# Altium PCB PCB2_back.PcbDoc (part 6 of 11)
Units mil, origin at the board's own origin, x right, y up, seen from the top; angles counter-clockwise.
Board outline 6299 x 3937 mil, 4 copper layers (TopLayer, GROUND, VCC, BottomLayer); 290 components, 470 nets, 2252 pads, 825 vias.
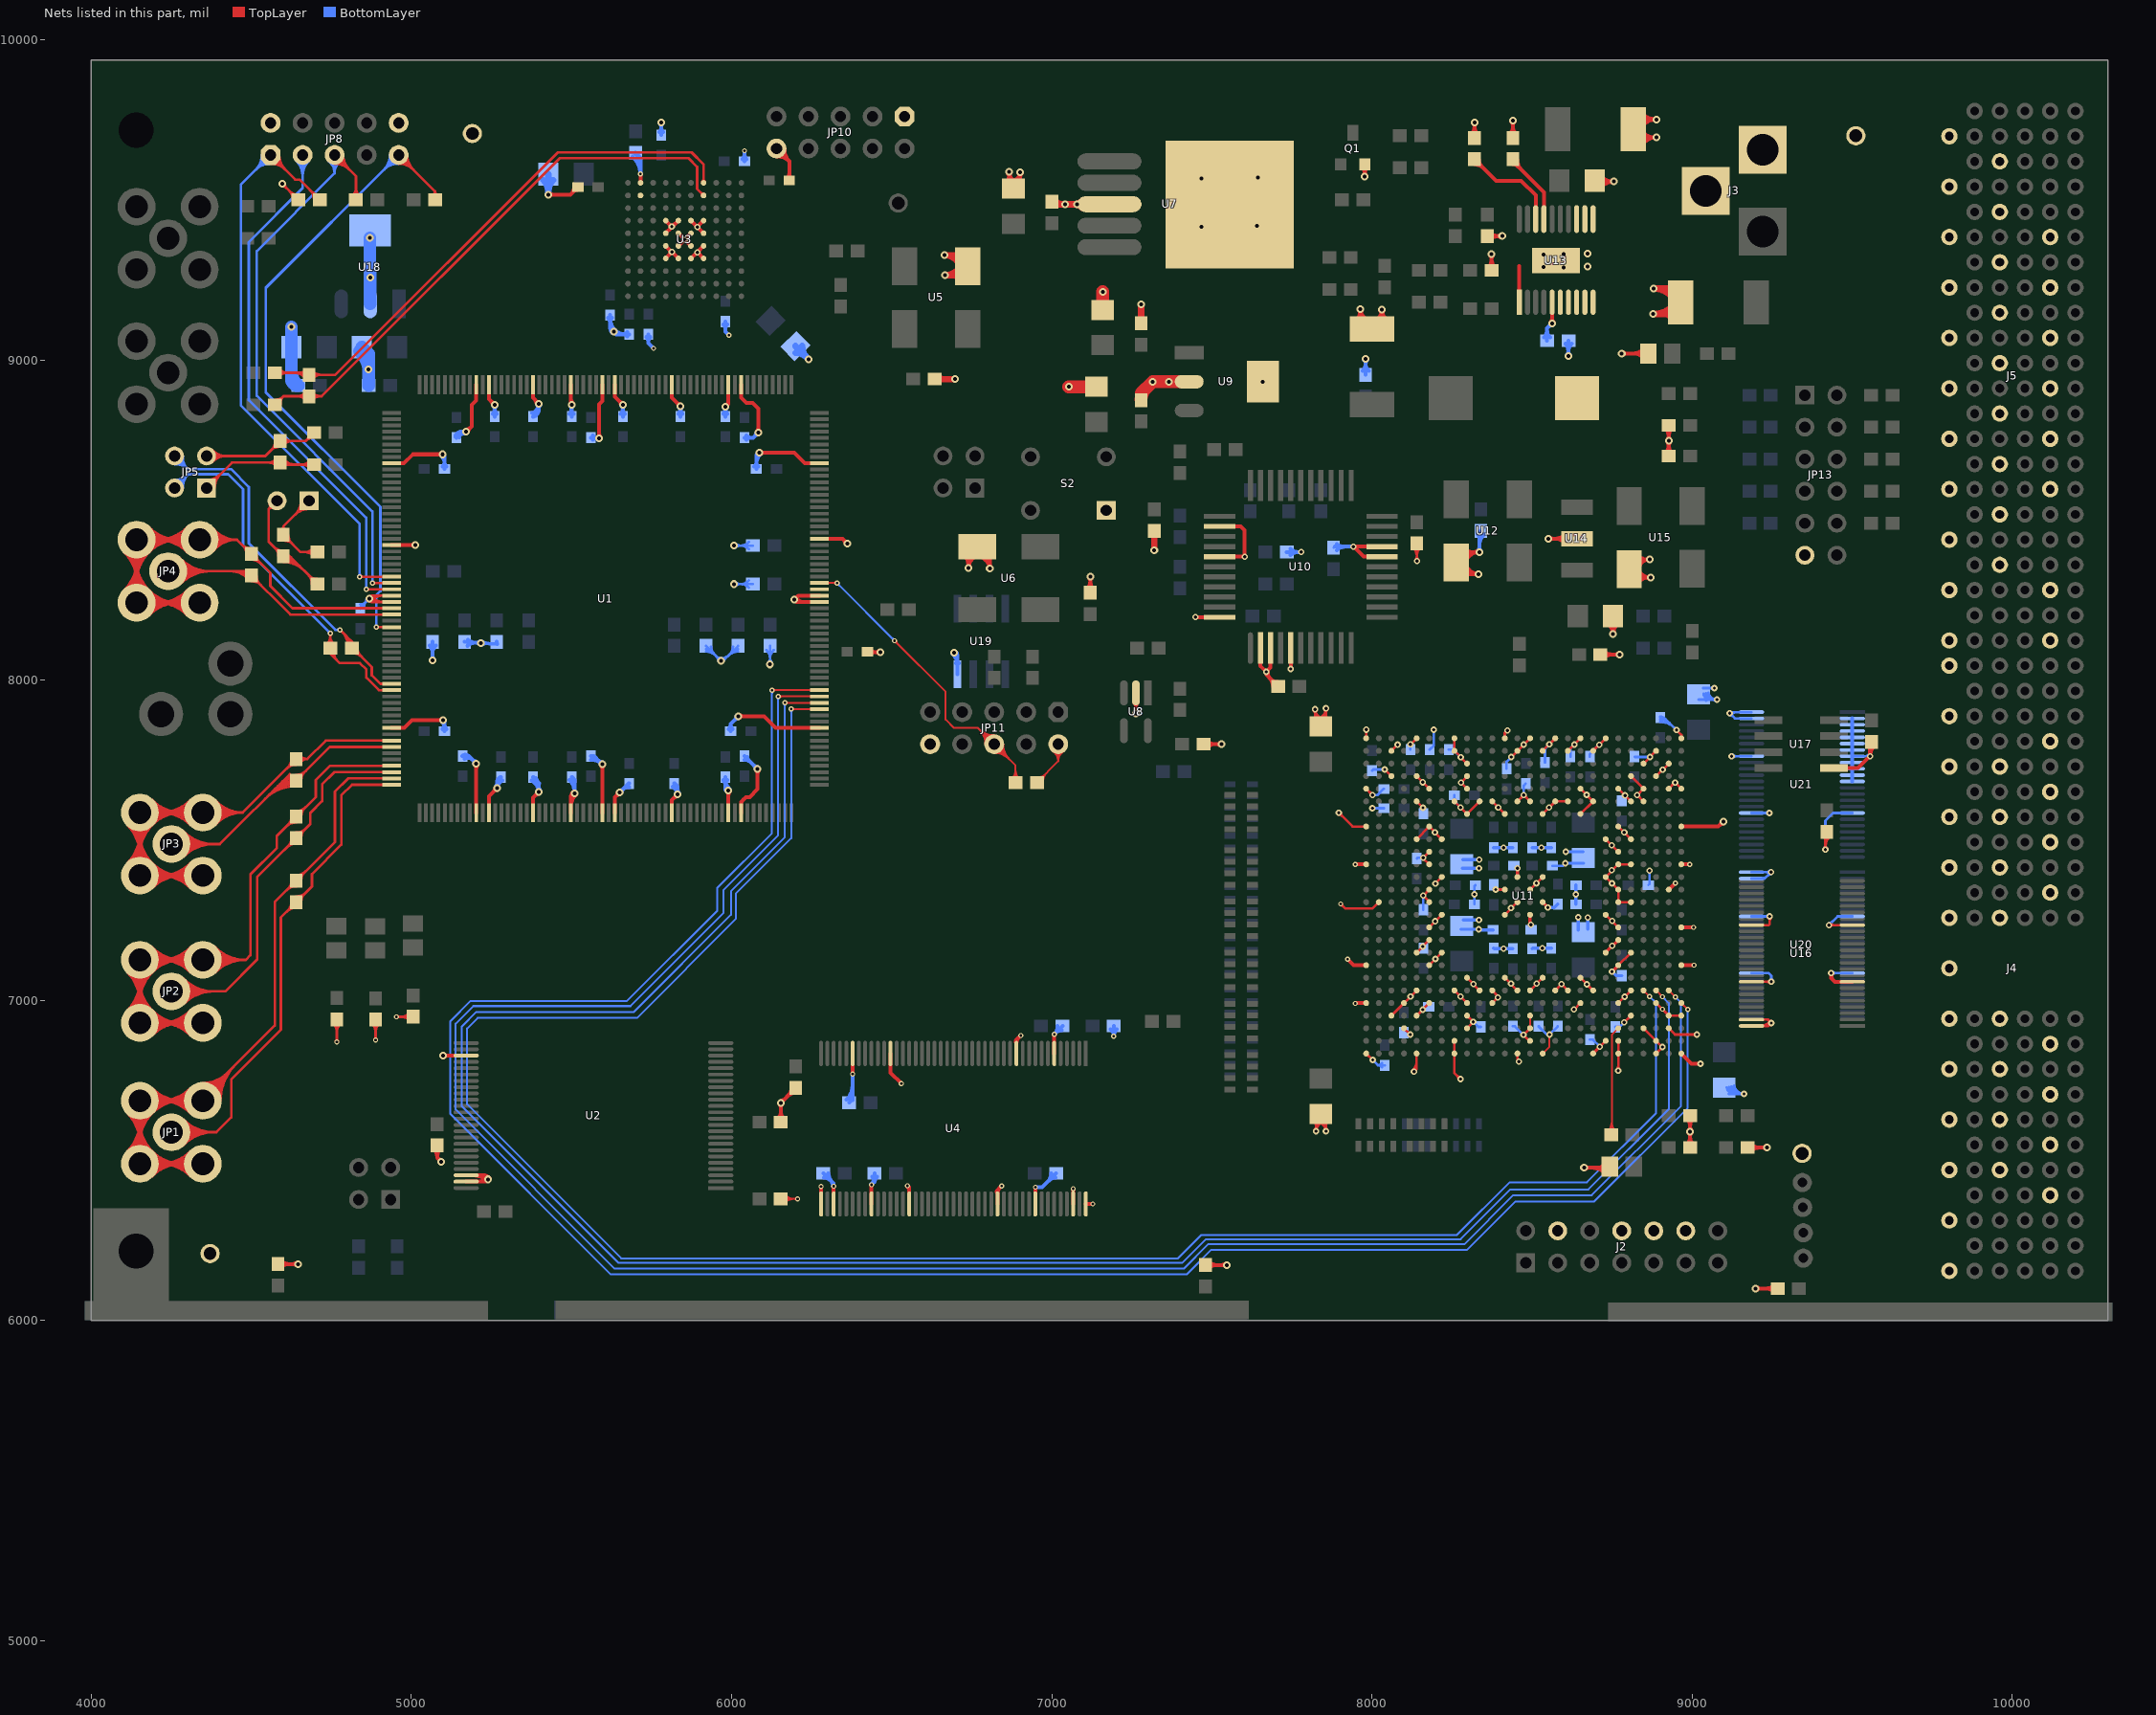
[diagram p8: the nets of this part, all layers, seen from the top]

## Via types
v1: diameter 16, hole 8, TopLayer to BottomLayer, 408 vias
v2: diameter 20, hole 10, TopLayer to BottomLayer, 221 vias
v3: diameter 24, hole 12, TopLayer to BottomLayer, 194 vias
v4: diameter 56.69, hole 56.69, TopLayer to BottomLayer, 2 vias

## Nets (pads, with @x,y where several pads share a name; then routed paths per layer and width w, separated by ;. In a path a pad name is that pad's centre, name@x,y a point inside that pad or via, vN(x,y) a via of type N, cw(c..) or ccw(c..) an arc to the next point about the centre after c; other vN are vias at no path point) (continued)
GND: (continued)
  BottomLayer w12: C42.1@5056.32,8107.89 cw(c5032.96,8084.53) 5066,8084.53 cw(c5099.04,8084.53) C42.1@5075.68,8107.89 ; v3@5061.76,8065.24 ccw(c5051.51,8075.49) 5066,8075.49 ccw(c5080.49,8075.49) v3@5070.24,8065.24 ; v3(5066,8061) C42.1@5066,8119.54 ; v3@5092.76,8700.76 cw(c5068.05,8676.05) 5102.99,8676.05 ; v3@5094.76,7870.76 cw(c5074.88,7850.88) C45.2@5102.99,7850.88 ; C45.2@5096.63,7846.36 ccw(c5081.26,7861.73) 5102.99,7861.73 ccw(c5124.72,7861.73) C45.2@5109.36,7846.36 ; C47.2@5096.63,8666.36 ccw(c5081.26,8681.73) 5102.99,8681.73 ccw(c5124.72,8681.73) C47.2@5109.36,8666.36 ; v3(5097,8705) 5102.99,8699.01 C47.2@5102.99,8660 ; v3(5099,7875) 5102.99,7871.01 C45.2@5102.99,7840 ; C48.2@5137.06,8760.09 cw(c5156.41,8756.28) 5156.41,8776 ; C48.2@5140,8757.01 5158.99,8776 ; C48.2@5140.26,8757.27 cw(c5171,8726.52) v3@5171,8770 ; C48.2@5140.23,8768.51 ccw(c5140.88,8794.11) 5158.99,8776 ; C48.2@5148.83,8757.77 cw(c5171,8753.41) v3(5171,8776) 5158.99,8776 ; C48.2@5149,8759.51 cw(c5164.69,8759.51) C48.2@5153.6,8770.6 ; C44.2@5158.11,7762.82 cw(c5168.58,7749.9) 5180.34,7761.66 ; C44.2@5160,7763.49 cw(c5160,7718.81) 5191.6,7750.4 ; C44.2@5165.67,7753.5 cw(c5177.01,7739.49) 5189.76,7752.24 ; C46.1@5166,8119.54 v3(5217,8116) 5267,8112 C50.2@5266,8119.54 ; C46.1@5174.98,8107.24 cw(c5201.08,8077.27) 5203.82,8116.91 ; C46.1@5176.32,8126.55 ccw(c5196.19,8143.84) 5194.37,8117.57 ; 5179.01,7762.99 v3(5202.46,7739.54) ; v3@5196.46,7739.54 ccw(c5181.97,7739.54) 5192.21,7749.79 ccw(c5202.46,7760.03) v3@5202.46,7745.54 ; v3@5212.47,8112.06 ccw(c5201.55,8102.55) 5202.55,8117 ccw(c5203.55,8131.45) v3@5213.06,8120.53 ; v3@5220.89,8111.43 cw(c5230.28,8100.41) 5231.44,8114.84 cw(c5232.59,8129.28) v3@5221.57,8119.89 ; C51.2@5253.64,8831.86 ccw(c5238.27,8847.22) 5260,8847.22 ccw(c5281.73,8847.22) C51.2@5266.36,8831.86 ; v3@5255.76,8854.76 cw(c5245.51,8844.51) 5260,8844.51 cw(c5274.49,8844.51) v3@5264.24,8854.76 ; C51.2@5260,8822.99 v3(5260,8859) ; v3@5262.76,7667.24 ccw(c5252.51,7677.49) 5267,7677.49 ccw(c5281.49,7677.49) v3@5271.24,7667.24 ; v3@5267,7660.42 cw(c5295.4,7660.42) C49.2@5283.71,7686.31 ; v3(5267,7663) 5267,7684.01 C49.2@5280,7697.01 ; 5267,7679.02 cw(c5287,7679.02) C49.2@5278.76,7697.24 ; C52.2@5375.45,7686.74 cw(c5352.45,7647.43) v3@5398,7647.43 ; C53.2@5377.06,8834 ccw(c5367.37,8862) v3(5397,8862) 5397,8839.99 ; C52.2@5380,7697.01 5398,7679.01 v3(5398,7651) ; C53.2@5380,8822.99 5397,8839.99 ; C52.2@5380.13,7685.51 cw(c5380.53,7659.04) 5399.25,7677.76 ; C53.2@5380.98,8822.66 ccw(c5373.2,8845.15) 5397,8845.15 ; C53.2@5381.03,8834.43 ccw(c5383.27,8853.72) 5397,8839.99 ; C52.2@5381.52,7697.1 cw(c5364.69,7668.35) 5398,7668.35 ; C52.2@5389,7694.51 ccw(c5404.69,7694.51) C52.2@5393.6,7683.41 ; C53.2@5389,8825.49 cw(c5404.69,8825.49) C53.2@5393.6,8836.59 ; v3@5392.76,8857.76 cw(c5382.51,8847.51) 5397,8847.51 cw(c5411.49,8847.51) v3@5401.24,8857.76 ; v3@5393.76,7655.24 ccw(c5383.51,7665.49) 5398,7665.49 ccw(c5412.49,7665.49) v3@5402.24,7655.24 ; C54.2@5493.64,7688.14 cw(c5456.54,7651.05) v3@5509,7651.05 ; C58.2@5493.64,8831.86 ccw(c5478.27,8847.22) 5500,8847.22 ccw(c5521.73,8847.22) C58.2@5506.36,8831.86 ; v3@5495.76,8855.76 cw(c5485.51,8845.51) 5500,8845.51 cw(c5514.49,8845.51) v3@5504.24,8855.76 ; C54.2@5500,7697.01 5509,7688.01 v3(5509,7646) ; C58.2@5500,8822.99 v3(5500,8860) ; C54.2@5502.12,7696.63 cw(c5485.52,7680.02) C54.2@5509,7680.02 ; v3@5504.76,7650.24 ccw(c5494.51,7660.49) 5509,7660.49 ccw(c5523.49,7660.49) v3@5513.24,7650.24 ; C56.2@5560,7751.49 cw(c5560,7699.57) v3@5596.72,7736.28 ; C56.2@5560,7762.99 5570.01,7762.99 v3(5596.16,7736.84) ; C56.2@5560,7763.49 cw(c5560,7740.54) 5576.23,7756.77 ; C57.2@5560,8757.01 5583.99,8757.01 v3(5586,8755) ; C57.2@5566.36,8750.64 cw(c5581.73,8735.28) 5581.73,8757.01 cw(c5581.73,8778.74) C57.2@5566.36,8763.37 ; C57.2@5566.67,8757.01 cw(c5566.67,8735.67) v3@5581.76,8750.76 ; v3@5590.16,7736.84 ccw(c5575.67,7736.84) 5585.91,7747.09 ccw(c5596.16,7757.33) v3@5596.16,7742.84 ; C59.1@5613.64,9131.14 cw(c5598.27,9115.77) 5620,9115.77 cw(c5641.73,9115.77) C59.1@5626.36,9131.14 ; 5620,9102.49 ccw(c5646.49,9102.49) v3@5627.76,9083.76 ; C59.1@5620,9131.46 ccw(c5675.46,9131.46) 5636.24,9092.24 ccw(c5665.8,9121.8) C62.1@5665.8,9080 ; C59.1@5620,9140 5620,9100 5640,9080 C62.1@5680,9080 ; v3@5626,9088 ccw(c5611.51,9088) 5621.76,9098.24 ccw(c5632,9108.49) v3@5632,9094 ; v3(5650,7649) 5678.01,7677.01 C60.2@5680,7677.01 ; v3@5650,7655 ccw(c5650,7669.49) 5660.24,7659.24 ccw(c5670.49,7649) v3@5656,7649 ; C61.2@5653.64,8831.86 ccw(c5638.27,8847.22) 5660,8847.22 ccw(c5681.73,8847.22) C61.2@5666.36,8831.86 ; v3@5655.76,8855.76 cw(c5645.51,8845.51) 5660,8845.51 cw(c5674.49,8845.51) v3@5664.24,8855.76 ; v3@5656.97,7655.97 cw(c5680,7632.94) C60.2@5680,7665.51 ; C61.2@5660,8822.99 v3(5660,8860) ; C62.1@5673.64,9073.64 ccw(c5658.27,9058.27) 5658.27,9080 ccw(c5658.27,9101.73) C62.1@5673.64,9086.36 ; C65.1@5733.64,9071.14 cw(c5718.27,9055.77) 5740,9055.77 cw(c5761.73,9055.77) C65.1@5746.36,9071.14 ; C65.1@5740,9080 5740,9052 v1(5756,9036) ; C66.1@5773.64,9710.86 ccw(c5758.27,9726.23) 5780,9726.23 ccw(c5801.73,9726.23) C66.1@5786.36,9710.86 ; v3@5775.76,9737.76 cw(c5765.51,9727.51) 5780,9727.51 cw(c5794.49,9727.51) v3@5784.24,9737.76 ; C66.1@5780,9702 v3(5780,9742) ; C63.2@5815.76,7666.57 cw(c5802.16,7641.14) v3@5831,7641.14 ; C63.2@5820,7677.01 5831,7666.01 v3(5831,7643) ; C63.2@5821.41,7677.15 cw(c5812.86,7661.16) C63.2@5831,7661.16 ; v3@5826.76,7647.24 ccw(c5816.51,7657.49) 5831,7657.49 ccw(c5845.49,7657.49) v3@5835.24,7647.24 ; C64.2@5833.64,8831.86 ccw(c5818.27,8847.22) 5840,8847.22 ccw(c5861.73,8847.22) C64.2@5846.36,8831.86 ; v3@5835.76,8850.76 cw(c5825.51,8840.51) 5840,8840.51 cw(c5854.49,8840.51) v3@5844.24,8850.76 ; C64.2@5840,8822.99 v3(5840,8855) ; C67.2@5973.64,7688.14 cw(c5958.27,7672.78) 5980,7672.78 cw(c6001.73,7672.78) C67.2@5986.36,7688.14 ; C69.2@5973.64,8831.86 ccw(c5958.27,8847.22) 5980,8847.22 ccw(c6001.73,8847.22) C69.2@5986.36,8831.86 ; C70.1@5973.64,9111.14 cw(c5958.27,9095.77) 5980,9095.77 cw(c6001.73,9095.77) C70.1@5986.36,9111.14 ; v3@5975.76,8849.76 cw(c5965.51,8839.51) 5980,8839.51 cw(c5994.49,8839.51) v3@5984.24,8849.76 ; 5980,7664.46 ccw(c5999.17,7664.46) v3@5985.62,7650.9 ; C67.2@5980,7693.43 ccw(c6028.14,7693.43) v3@5994.1,7659.38 ; C67.2@5980,7697.01 5980,7665 ; C69.2@5980,8822.99 v3(5980,8854) ; C70.1@5980,9120 5980,9089 v1(5992,9077) ; v3@5983.86,7655.31 ccw(c5970.67,7655.67) 5980,7665 ; v3@5989.69,7661.14 cw(c5989.33,7674.33) 5980,7665 ; v3(5989.86,7655.14) 5980,7665 ; C71.2@5990.64,7846.36 ccw(c5975.28,7861.73) 5997.01,7861.73 ccw(c6018.74,7861.73) C71.2@6003.37,7846.36 ; C71.2@5997.01,7840 5997.01,7863.01 v3(6021,7887) ; v3@6015,7887 cw(c6000.51,7887) 6010.76,7876.76 cw(c6021,7866.51) v3@6021,7881 ; C74.1@6033.64,9626.36 ccw(c6018.27,9641.73) 6040,9641.73 ccw(c6061.73,9641.73) C74.1@6046.36,9626.36 ; C75.2@6040,7751.49 cw(c6040,7723.73) 6059.63,7743.36 ; C75.2@6040,7762.99 v3(6081,7721.99) ; C77.2@6040,8757.01 6067.01,8757.01 v3(6083,8773) ; C74.1@6040,9620 v1(6040,9653) ; C77.2@6046.36,8750.64 cw(c6061.73,8735.28) 6061.73,8757.01 cw(c6061.73,8778.74) C77.2@6046.36,8763.37 ; C75.2@6049,7760.49 ccw(c6064.69,7760.49) C75.2@6053.6,7749.4 ; C73.2@6070.64,8666.36 ccw(c6055.28,8681.73) 6077.01,8681.73 ccw(c6098.74,8681.73) C73.2@6083.37,8666.36 ; v3@6075,7721.99 ccw(c6060.51,7721.99) 6070.76,7732.23 ccw(c6081,7742.48) v3@6081,7727.99 ; C73.2@6077.01,8660 6077.01,8701.01 ; C73.2@6077.01,8673.81 cw(c6122.19,8673.81) v3@6090.24,8705.76 ; v3@6077,8773 cw(c6062.51,8773) 6072.76,8762.76 cw(c6083,8752.51) v3@6083,8767 ; v3@6080.03,8709.42 cw(c6069.6,8708.42) 6077.01,8701.01 ; v3@6085.42,8704.03 ccw(c6084.42,8693.6) 6077.01,8701.01 ; v3(6086,8710) 6077.01,8701.01 ; C79.1@6286.54,6460 6318.6,6427.94 v1(6318.6,6419.4) ; C79.1@6288.5,6446.32 cw(c6288.5,6418.03) 6308.51,6438.03 ; C79.1@6302.19,6460 ccw(c6339.98,6460) 6313.26,6433.28 ; 6309.15,6437.39 cw(c6291.17,6419.4) v1@6316.6,6419.4 ; C80.1@6358.83,6689.68 ccw(c6313.37,6735.13) 6377.65,6735.13 ; C80.1@6367.31,6681.19 ccw(c6342.34,6706.16) 6377.65,6706.16 ; C80.1@6377.65,6688.88 v1(6377.65,6769.35) ; v1@6435.3,6425.12 ccw(c6408.16,6452.26) C81.1@6446.54,6452.26 ; v1(6436.71,6423.71) 6446.54,6433.54 ; C81.1@6438.63,6448.83 cw(c6427.79,6433.54) 6446.54,6433.54 ; C81.1@6446.54,6460 6446.54,6433.54 ; C81.1@6454.45,6448.83 ccw(c6465.28,6433.54) 6446.54,6433.54 ; v3@6690.76,8080.76 cw(c6656.37,8046.37) U19.4@6705,8046.37 ; v3(6695,8085) 6705,8075 ; v3@6695.1,8079 cw(c6695.34,8065.34) 6705,8075 ; v3@6699.24,8089.24 cw(c6685.34,8075.34) 6705,8075.34 ; U19.4@6700.89,8053.24 ccw(c6690.97,8063.16) 6705,8063.16 ccw(c6719.03,8063.16) U19.4@6709.11,8053.24 ; v3@6701,8084.9 ccw(c6714.66,8084.66) 6705,8075 ; U19.4@6705,8017.64 6705,8075 ; v1(6948.52,6416.52) 6969.98,6416.52 C82.1@7013.46,6460 ; 6986.74,6433.28 ccw(c6960.02,6460) C82.1@6997.81,6460 ; 6991.49,6438.03 cw(c7011.5,6418.03) C82.1@7011.5,6446.32 ; v1(7007.57,6894.11) C83.1@7033.46,6920 ; v1@7008.56,6895.1 ccw(c6986.07,6917.58) C83.1@7017.83,6919.27 ; v1@7011.49,6898.03 cw(c7031.5,6878.03) C83.1@7031.5,6906.32 ; C84.1@7183.89,6910.22 cw(c7161.64,6887.47) v1(7193.46,6887.46) ; C84.1@7193.46,6920 v1(7193.46,6887.46) ; C84.1@7203.03,6910.22 ccw(c7225.29,6887.47) v1(7193.46,6887.46) ; C86.1@7733.46,8400 v2(7779,8400) ; C86.1@7745.11,8390.32 cw(c7768.47,8366.96) 7768.47,8400 cw(c7768.47,8433.04) C86.1@7745.11,8409.68 ; C89.1@7883.46,8416.93 v2(7941.93,8416.93) ; C89.1@7889.68,8405.76 cw(c7916.65,8378.78) 7916.65,8416.93 ; C89.1@7889.68,8425.11 ccw(c7909.43,8444.86) 7909.43,8416.93 ; C92.1@7970.32,8965.11 ccw(c7946.96,8988.47) 7980,8988.47 ccw(c8013.04,8988.47) C92.1@7989.68,8965.11 ; v3@7975.76,8998.76 cw(c7965.51,8988.51) 7980,8988.51 cw(c7994.49,8988.51) v3@7984.24,8998.76 ; C92.1@7980,8953.46 v3(7980,9003) ; C117.1@8330.32,8454.89 cw(c8319.03,8443.6) 8335,8443.6 ; v3@8330.76,8404.24 ccw(c8320.51,8414.49) 8335,8414.49 ccw(c8349.49,8414.49) v3@8339.24,8404.24 ; v3(8335,8400) 8335,8461.54 C117.1@8340,8466.54 ; 8335,8419.46 cw(c8385.11,8419.46) C117.1@8349.68,8454.89 ; U21.12@9500,7683.47 U21.2@9500,7880.31
  BottomLayer w20: v3@4866.54,8969.46 v3@4866.54,8970 ; C55.2@5412,9560.86 cw(c5375.3,9524.17) 5427.2,9524.17 cw(c5479.09,9524.17) C55.2@5442.4,9560.86 ; v3(5427.2,9516.2) C55.2@5427.2,9580 ; C78.2@6198.97,9021.84 cw(c6198.97,8969.95) 6235.67,9006.64 cw(c6272.37,9043.34) C78.2@6220.47,9043.34 ; C78.2@6198.97,9043.34 v3(6240.31,9002)
  BottomLayer w40: 4624.88,8966.76 ccw(c4691.33,8966.76) C39.1@4644.34,8919.78 ; v3(4624.88,9102.88) 4624.88,8941.65 ; C39.1@4644.53,8919.69 cw(c4646.98,8941.65) 4624.88,8941.65 ; C39.1@4646.54,8920 4624.88,8941.65 ; C43.2@4837.55,9027.21 cw(c4787.45,8966.71) v3@4866,8966.71 ; C43.2@4844.88,9040 4866,9018.88 v3(4866,8970) 4866.54,8969.46 C41.1@4866.54,8920 ; v3(4870,9381) U18.2@4871,9175
  other v1: 8906.68,6972.06
  other v2: 8158.11,6970.99 8789,7011 8120.43,7012.05 8276.51,7011.68 8316.5,7050.42 8671,7050 8434,7052 8514,7052 8198.14,7129.13 8411,7160.99 8532,7162.99 8158.45,7168.18 8750,7170 8197,7247 8750,7248 8434,7288 8320,7331 8637.01,7331 8749.46,7365.5 8513.29,7365.54 8749,7406 8411,7477.01 8529,7477.01 8748.71,7484.36 8788,7524 8196.61,7524.65 8394,7602 8553.21,7602.31 8790,7640 8670.04,7641.77 8158.49,7680.88 8907.77,7720.65 5813.2,9337.06
  other v3: 8993.47,6590 8926.54,8747 7366,8932 7659,8932 5632,9088 4871,9257 8599,9288 8536,9290 8673,9292 8535,9329 8599,9330 8673,9332 7467,9415 7641,9419 7042,9486 7078,9486 7467,9567 7643,9569
GP02: R51.1 U11.C6 | length 445.9
  TopLayer w6: R51.1@8736.71,6591.8 ccw(c8707.03,6621.48) 8749,6621.48 ; R51.1@8740.95,6587.56 ccw(c8721.51,6606.99) 8749,6606.99 ; R51.1@8746.54,6580 8749,6582.46 8749,6892.59 U11.C6@8769.15,6912.74 ; 8749,6604.6 ccw(c8773.1,6604.6) R51.1@8756.06,6587.56 ; 8749,6619.08 ccw(c8787.59,6619.08) R51.1@8760.3,6591.8
GP04: U1.13 U11.F4 | length 6581.4
  TopLayer w6: v1(6186,7909.51) U1.13@6274.31,7909.51 ; v1@6189.54,7905.98 cw(c6198.07,7897.44) 6198.07,7909.51 cw(c6198.07,7921.58) v1@6189.54,7913.05 ; U1.13@6248.63,7907.46 ccw(c6243.67,7902.5) 6243.67,7909.51 ccw(c6243.67,7916.53) U1.13@6248.63,7911.57 ; U11.F4@8847.89,7030.85 v1(8867,7011.74)
  BottomLayer w6: v1@6182.46,7905.98 cw(c6173.93,7897.44) 6186,7897.44 cw(c6198.07,7897.44) v1@6189.54,7905.98 ; v1(6186,7909.51) 6186,7506 6013,7333 6013,7254 5704,6945 5207,6945 5174,6912 5174,6675 5655,6194 7394,6194 7467,6267 8265,6267 8430,6432 8671,6432 8887,6648 8887,6991.74 v1(8867,7011.74)
GP05: U1.14 U11.F3 | length 6681.7
  TopLayer w6: v1(6166,7929.2) U1.14@6274.31,7929.2 ; v1@6169.54,7925.66 cw(c6178.07,7917.13) 6178.07,7929.2 cw(c6178.07,7941.27) v1@6169.54,7932.73 ; U1.14@6248.63,7927.14 ccw(c6243.67,7922.18) 6243.67,7929.2 ccw(c6243.67,7936.21) U1.14@6248.63,7931.25 ; U11.F3@8887.26,7030.85 v1(8907,7011.11)
  BottomLayer w6: v1@6162.46,7925.66 cw(c6153.93,7917.13) 6166,7917.13 cw(c6178.07,7917.13) v1@6169.54,7925.66 ; v1(6166,7929.2) 6166,7509 5998,7341 5998,7267 5695,6964 5203,6964 5157,6918 5157,6670 5647,6180 7407,6180 7481,6254 8277,6254 8432,6409 8676,6409 8927,6660 8927,6991.11 v1(8907,7011.11)
GP06: U1.15 U11.F2 | length 6792.9
  TopLayer w6: v1(6145,7948.88) U1.15@6274.31,7948.88 ; v1@6148.54,7945.35 cw(c6157.07,7936.81) 6157.07,7948.88 cw(c6157.07,7960.95) v1@6148.54,7952.42 ; U1.15@6248.63,7946.83 ccw(c6243.67,7941.87) 6243.67,7948.88 ccw(c6243.67,7955.9) U1.15@6248.63,7950.94 ; U11.F2@8926.63,7030.85 v1(8947,7010.48)
  BottomLayer w6: v1@6141.46,7945.35 cw(c6132.93,7936.81) 6145,7936.81 cw(c6157.07,7936.81) v1@6148.54,7945.35 ; v1(6145,7948.88) 6145,7515 5974,7344 5974,7272 5684,6982 5193,6982 5138,6927 5138,6659 5635,6162 7412,6162 7488,6238 8288,6238 8441.27,6391.27 8686.27,6391.27 8965,6670 8965,6992.48 v1(8947,7010.48)
GP07: U1.16 U11.E1 | length 6846.1
  TopLayer w6: v1(6126,7968.57) U1.16@6274.31,7968.57 ; v1@6129.54,7965.03 cw(c6138.07,7956.5) 6138.07,7968.57 cw(c6138.07,7980.64) v1@6129.54,7972.1 ; U1.16@6248.63,7966.51 ccw(c6243.67,7961.55) 6243.67,7968.57 ccw(c6243.67,7975.58) U1.16@6248.63,7970.62 ; U11.E1@8966,6991.48 v1(8986,6971.48)
  BottomLayer w6: v1@6122.46,7965.03 cw(c6113.93,7956.5) 6126,7956.5 cw(c6138.07,7956.5) v1@6129.54,7965.03 ; v1(6126,7968.57) 6126,7522 5955,7351 5955,7280 5673,6998 5185,6998 5121,6934 5121,6646 5623,6144 7421,6144 7497,6220 8296,6220 8448.02,6372.02 8694.02,6372.02 8986,6664 v1(8986,6971.48)
IN1+: C2.1 R13.1 U3.A7 | length 1926
  TopLayer w8: C2.1@4573.46,8960 4673.46,8960 R13.1@4680,8953.46 4762.13,8953.46 5456.67,9648 5875,9648 5912.22,9610.78 U3.A7@5912.22,9553 ; C2.1@4586.52,8948.91 cw(c4613.3,8922.13) 4613.3,8960 cw(c4613.3,8997.87) C2.1@4586.52,8971.09 ; 4631.11,8960 cw(c4631.11,8906.54) R13.1@4668.91,8944.34 ; 4650.42,8960 cw(c4650.42,8925.85) R13.1@4674.57,8950 ; 4653.16,8960 ccw(c4653.16,8982.27) R13.1@4668.91,8966.52 ; R13.1@4691.09,8942.37 cw(c4717.87,8915.6) 4717.87,8953.46 cw(c4717.87,8991.33) R13.1@4691.09,8964.56 ; U3.A7@5908.79,9556.44 ccw(c5900.49,9564.73) 5912.22,9564.73 ccw(c5923.95,9564.73) U3.A7@5915.66,9556.44
IN1-: C1.1 R13.2 U3.B7 | length 1937.2
  TopLayer w8: C1.1@4573.46,8860 4600,8886.54 ; C1.1@4575.43,8875.68 ccw(c4575.43,8908.8) 4598.85,8885.38 ; C1.1@4591.04,8861.53 cw(c4621.98,8864.56) 4600,8886.53 ; R13.2@4668.91,8875.44 ccw(c4642.13,8848.67) 4642.13,8886.54 ccw(c4642.13,8924.4) R13.2@4668.91,8897.63 ; R13.2@4691.09,8875.44 cw(c4717.87,8848.67) 4717.87,8886.54 cw(c4717.87,8924.4) R13.2@4691.09,8897.63 ; U3.B7@5907.36,9513.63 ccw(c5895.63,9513.63) 5903.93,9521.92 ccw(c5912.22,9530.22) U3.B7@5912.22,9518.49 ; U3.B7@5912.22,9513.63 5892,9533.85 5892,9603 5865,9630 5463,9630 4719.54,8886.54 4600,8886.54
IN2+: R66.1 U3.A2 | length 205
  TopLayer w12: U3.A2@5715.37,9553 v1(5715.37,9580.37)
  BottomLayer w12: R66.1@5690.76,9634.47 cw(c5639.55,9578.56) v1@5715.37,9578.56 ; R66.1@5698.86,9643.32 cw(c5664.52,9605.82) 5715.37,9605.82 ; R66.1@5700,9646.54 5715.37,9631.17 v1(5715.37,9580.37)
IN2-: U3.B2
JTAG_TCK: JP8.1 R14.2 U1.147 | length 2277.4
  TopLayer w8: JP8.1@4560,9613 cw(c4560,9547.82) 4606.09,9593.91 cw(c4652.18,9640) JP8.1@4587,9640 ; JP8.1@4560,9621 cw(c4560,9575.13) 4592.44,9607.56 cw(c4624.87,9640) JP8.1@4579,9640 ; JP8.1@4560,9640 4637,9563 4650.46,9563 R14.2@4713.46,9500 ; 4683.33,9530.14 cw(c4653.19,9500) R14.2@4695.81,9500 ; 4688.08,9525.38 ccw(c4711.5,9548.8) R14.2@4711.5,9515.68 ; R14.2@4696.99,9516.48 cw(c4680.51,9500) R14.2@4703.81,9500 ; v1(4838.1,8322.9) U1.147@4937.69,8322.9 ; v1@4840.93,8320.07 cw(c4847.76,8313.24) 4847.76,8322.9 cw(c4847.76,8332.55) v1@4840.93,8325.73
  BottomLayer w8: JP8.1@4533,9640 cw(c4467.82,9640) 4513.91,9593.91 cw(c4560,9547.82) JP8.1@4560,9613 ; JP8.1@4541,9640 cw(c4495.13,9640) 4527.56,9607.56 cw(c4560,9575.13) JP8.1@4560,9621 ; JP8.1@4560,9640 4467,9547 4467,8858 4838.1,8486.9 v1(4838.1,8322.9) ; v1@4835.27,8325.73 ccw(c4828.45,8332.55) 4838.1,8332.55 ccw(c4847.76,8332.55) v1@4840.93,8325.73
JTAG_TDI: JP8.9 R18.1 U1.155 | length 2445.3
  TopLayer w8: v1(4890,8165.42) U1.155@4937.69,8165.42 ; v1@4892.83,8162.59 cw(c4899.66,8155.76) 4899.66,8165.42 cw(c4899.66,8175.07) v1@4892.83,8168.25 ; JP8.9@4960,9613 cw(c4960,9547.82) 5006.09,9593.91 cw(c5052.18,9640) JP8.9@4987,9640 ; JP8.9@4960,9621 cw(c4960,9575.13) 4992.44,9607.56 cw(c5024.87,9640) JP8.9@4979,9640 ; JP8.9@4960,9640 5073.46,9526.54 ; R18.1@5065.9,9513.74 ccw(c5058.86,9526.53) 5073.46,9526.53 ; R18.1@5073.46,9500 5073.46,9526.54 ; R18.1@5081.03,9513.74 cw(c5088.07,9526.53) 5073.46,9526.53
  BottomLayer w8: v1@4887.17,8168.25 ccw(c4880.34,8175.07) 4890,8175.07 ccw(c4899.66,8175.07) v1@4892.83,8168.25 ; v1(4890,8165.42) 4890,8265 4903,8278 4903,8541 4545,8899 4545,9225 JP8.9@4960,9640 ; JP8.9@4933,9640 cw(c4867.82,9640) 4913.91,9593.91 cw(c4960,9547.82) JP8.9@4960,9613 ; JP8.9@4941,9640 cw(c4895.13,9640) 4927.56,9607.56 cw(c4960,9575.13) JP8.9@4960,9621
JTAG_TDO: JP8.3 U1.149 | length 1861.9
  TopLayer w8: v1(4858.47,8283.53) U1.149@4937.69,8283.53 ; v1@4861.3,8280.7 cw(c4868.13,8273.87) 4868.13,8283.53 cw(c4868.13,8293.18) v1@4861.3,8286.36
  BottomLayer w8: JP8.3@4640.91,9620.91 cw(c4594.82,9574.82) 4660,9574.82 cw(c4725.18,9574.82) JP8.3@4679.09,9620.91 ; JP8.3@4646.56,9626.56 cw(c4614.13,9594.13) 4660,9594.13 cw(c4705.87,9594.13) JP8.3@4673.44,9626.56 ; JP8.3@4660,9640 4660,9536 4492,9368 4492,8874 4858.47,8507.53 v1(4858.47,8283.53) ; v1@4855.64,8286.36 ccw(c4848.82,8293.18) 4858.47,8293.18 ccw(c4868.13,8293.18) v1@4861.3,8286.36
JTAG_TMS: JP8.5 R15.1 U1.148 | length 2219.2
  TopLayer w8: JP8.5@4760,9613 cw(c4760,9547.82) 4806.09,9593.91 cw(c4852.18,9640) JP8.5@4787,9640 ; JP8.5@4760,9621 cw(c4760,9575.13) 4792.44,9607.56 cw(c4824.87,9640) JP8.5@4779,9640 ; JP8.5@4760,9640 4826.54,9573.46 R15.1@4826.54,9500 ; R15.1@4815.44,9511.09 ccw(c4788.67,9537.87) 4826.54,9537.87 ccw(c4864.4,9537.87) R15.1@4837.63,9511.09 ; v1(4878,8303.21) U1.148@4937.69,8303.21 ; v1@4880.83,8300.38 cw(c4887.66,8293.56) 4887.66,8303.21 cw(c4887.66,8312.87) v1@4880.83,8306.04
  BottomLayer w8: JP8.5@4742.9,9619.11 cw(c4713.34,9583) 4760,9583 ; JP8.5@4747.96,9625.3 cw(c4727.16,9599.89) 4760,9599.89 cw(c4792.84,9599.89) JP8.5@4772.04,9625.3 ; JP8.5@4760,9640 4760,9583 ; JP8.5@4777.1,9619.11 ccw(c4806.66,9583) 4760,9583 ; v1@4875.17,8306.04 ccw(c4868.34,8312.87) 4878,8312.87 ccw(c4887.66,8312.87) v1@4880.83,8306.04 ; v1(4878,8303.21) 4878,8527 4517,8888 4517,9340 4760,9583
LVDS1_INN: JP1.2 R1.1 U1.179 | length 6666.2
  TopLayer w8: JP1.2@4112.65,6528.5 ccw(c4018.66,6622.49) 4151.57,6622.49 ccw(c4284.49,6622.49) 4190.5,6528.5 ccw(c4284.49,6622.49) 4284.49,6489.57 ccw(c4284.49,6356.66) JP1.2@4190.5,6450.65 ; JP1.2@4112.65,6647.5 cw(c4018.66,6553.51) 4151.57,6553.51 cw(c4284.49,6553.51) 4190.5,6647.5 cw(c4284.49,6553.51) 4284.49,6686.43 cw(c4284.49,6819.34) JP1.2@4190.5,6725.35 ; JP1.2@4118.3,6522.85 ccw(c4037.97,6603.18) 4151.57,6603.18 ccw(c4265.18,6603.18) 4184.85,6522.85 ccw(c4265.18,6603.18) 4265.18,6489.57 ccw(c4265.18,6375.97) JP1.2@4184.85,6456.3 ; JP1.2@4118.3,6653.15 cw(c4037.97,6572.82) 4151.57,6572.82 cw(c4265.18,6572.82) 4184.85,6653.15 cw(c4265.18,6572.82) 4265.18,6686.43 cw(c4265.18,6800.03) JP1.2@4184.85,6719.7 ; JP1.2@4123.96,6517.19 ccw(c4057.29,6583.86) 4151.57,6583.86 ccw(c4245.86,6583.86) 4179.19,6517.19 ccw(c4245.86,6583.86) 4245.86,6489.58 ccw(c4245.86,6395.29) JP1.2@4179.19,6461.96 ; JP1.2@4123.96,6658.81 cw(c4057.29,6592.14) 4151.57,6592.14 cw(c4245.86,6592.14) 4179.19,6658.81 cw(c4245.86,6592.14) 4245.86,6686.42 cw(c4245.86,6780.71) JP1.2@4179.19,6714.04 ; JP1.2@4129.62,6511.53 ccw(c4076.6,6564.55) 4151.57,6564.55 ccw(c4226.55,6564.55) 4173.53,6511.53 ccw(c4226.55,6564.55) 4226.55,6489.57 ccw(c4226.55,6414.6) JP1.2@4173.53,6467.62 ; JP1.2@4129.62,6664.47 cw(c4076.6,6611.45) 4151.57,6611.45 cw(c4226.55,6611.45) 4173.53,6664.47 cw(c4226.55,6611.45) 4226.55,6686.43 cw(c4226.55,6761.4) JP1.2@4173.53,6708.38 ; JP1.2@4309.5,6450.65 ccw(c4215.51,6356.66) 4215.51,6489.57 ccw(c4215.51,6622.49) JP1.2@4309.5,6528.5 ; JP1.2@4309.5,6647.5 ccw(c4215.51,6553.51) 4215.51,6686.43 ccw(c4215.51,6819.34) JP1.2@4309.5,6725.35 ; JP1.2@4315.15,6456.3 ccw(c4234.82,6375.97) 4234.82,6489.57 ccw(c4234.82,6603.18) JP1.2@4315.15,6522.85 ; JP1.2@4315.15,6653.15 ccw(c4234.82,6572.82) 4234.82,6686.43 ccw(c4234.82,6800.03) JP1.2@4315.15,6719.7 ; JP1.2@4320.81,6461.96 ccw(c4254.14,6395.29) 4254.14,6489.57 ccw(c4254.14,6583.86) JP1.2@4320.81,6517.19 ; JP1.2@4320.81,6658.81 ccw(c4254.14,6592.14) 4254.14,6686.42 ccw(c4254.14,6780.71) JP1.2@4320.81,6714.04 ; JP1.2@4326.47,6467.62 ccw(c4273.45,6414.6) 4273.45,6489.57 ccw(c4273.45,6564.55) JP1.2@4326.47,6511.53 ; JP1.2@4326.47,6664.47 ccw(c4273.45,6611.45) 4273.45,6686.43 ccw(c4273.45,6761.4) JP1.2@4326.47,6708.38 ; JP1.2@4348.43,6489.57 JP1.2@4151.57,6489.57 JP1.2@4151.57,6686.43 4338,6686.43 4573,6921.43 4573,7306.46 4761,7494.46 4761,7652 4801.98,7692.98 U1.179@4937.69,7692.98 ; JP1.2@4348.43,6725.48 ccw(c4348.43,6794.6) 4397.3,6745.72 ; JP1.2@4348.43,6733.48 ccw(c4348.43,6821.91) 4410.96,6759.38 ; JP1.2@4348.43,6741.48 ccw(c4348.43,6849.23) 4424.61,6773.04 ; JP1.2@4371.48,6686.43 cw(c4452.31,6686.43) 4395.15,6743.58 ; JP1.2@4379.48,6686.43 cw(c4479.62,6686.43) 4408.81,6757.24 ; JP1.2@4387.48,6686.43 cw(c4506.94,6686.43) 4422.47,6770.89 ; JP1.2@4395.48,6686.43 cw(c4534.25,6686.43) 4436.12,6784.55 ; JP1.2@4403.48,6686.43 cw(c4561.56,6686.43) 4449.78,6798.21 ; 4609.86,7343.33 cw(c4640,7313.19) R1.1@4640,7355.81 ; 4614.62,7348.08 ccw(c4591.2,7371.5) R1.1@4624.31,7371.5 ; R1.1@4623.52,7356.98 cw(c4640,7340.51) R1.1@4640,7363.81 ; R1.1@4640,7383.12 ccw(c4640,7406.42) R1.1@4656.48,7389.94 ; R1.1@4640,7391.12 ccw(c4640,7433.74) 4670.14,7403.6 ; R1.1@4655.69,7375.43 cw(c4688.8,7375.43) 4665.38,7398.85
LVDS1_INP: JP1.1 R1.2 U1.180 | length 2333.7
  TopLayer w8: JP1.1@4250,6588 4391,6588 4437,6634 4437,6753 4592,6908 4592,7258.54 4689,7355.54 4689,7394 4781,7486 4781,7640 4814.29,7673.29 U1.180@4937.69,7673.29 ; JP1.1@4271.96,6566.04 cw(c4324.97,6513.03) 4324.97,6588 cw(c4324.97,6662.97) JP1.1@4271.96,6609.96 ; JP1.1@4277.62,6560.38 cw(c4344.29,6493.71) 4344.29,6588 cw(c4344.29,6682.29) JP1.1@4277.62,6615.62 ; JP1.1@4283.27,6554.73 cw(c4363.6,6474.4) 4363.6,6588 cw(c4363.6,6701.6) JP1.1@4283.27,6621.27 ; JP1.1@4288.93,6549.07 cw(c4382.91,6455.09) 4382.91,6588 cw(c4382.91,6720.91) JP1.1@4288.93,6626.93 ; 4609.86,7276.4 cw(c4640,7246.26) R1.2@4640,7288.88 ; 4614.62,7281.15 ccw(c4591.2,7304.57) R1.2@4624.31,7304.57 ; R1.2@4623.52,7290.06 cw(c4640,7273.58) R1.2@4640,7296.88 ; R1.2@4640,7316.19 ccw(c4640,7339.49) R1.2@4656.48,7323.02 ; R1.2@4640,7324.19 ccw(c4640,7366.81) 4670.14,7336.67 ; R1.2@4655.69,7308.5 cw(c4688.8,7308.5) 4665.38,7331.92
LVDS2_INN: JP2.2 R7.1 U1.177 | length 6359
  TopLayer w8: JP2.2@4112.65,6968.5 ccw(c4018.66,7062.49) 4151.57,7062.49 ccw(c4284.49,7062.49) 4190.5,6968.5 ccw(c4284.49,7062.49) 4284.49,6929.57 ccw(c4284.49,6796.66) JP2.2@4190.5,6890.65 ; JP2.2@4112.65,7087.5 cw(c4018.66,6993.51) 4151.57,6993.51 cw(c4284.49,6993.51) 4190.5,7087.5 cw(c4284.49,6993.51) 4284.49,7126.43 cw(c4284.49,7259.34) JP2.2@4190.5,7165.35 ; JP2.2@4118.3,6962.85 ccw(c4037.97,7043.18) 4151.57,7043.18 ccw(c4265.18,7043.18) 4184.85,6962.85 ccw(c4265.18,7043.18) 4265.18,6929.57 ccw(c4265.18,6815.97) JP2.2@4184.85,6896.3 ; JP2.2@4118.3,7093.15 cw(c4037.97,7012.82) 4151.57,7012.82 cw(c4265.18,7012.82) 4184.85,7093.15 cw(c4265.18,7012.82) 4265.18,7126.43 cw(c4265.18,7240.03) JP2.2@4184.85,7159.7 ; JP2.2@4123.96,6957.19 ccw(c4057.29,7023.86) 4151.57,7023.86 ccw(c4245.86,7023.86) 4179.19,6957.19 ccw(c4245.86,7023.86) 4245.86,6929.58 ccw(c4245.86,6835.29) JP2.2@4179.19,6901.96 ; JP2.2@4123.96,7098.81 cw(c4057.29,7032.14) 4151.57,7032.14 cw(c4245.86,7032.14) 4179.19,7098.81 cw(c4245.86,7032.14) 4245.86,7126.42 cw(c4245.86,7220.71) JP2.2@4179.19,7154.04 ; JP2.2@4129.62,6951.53 ccw(c4076.6,7004.55) 4151.57,7004.55 ccw(c4226.55,7004.55) 4173.53,6951.53 ccw(c4226.55,7004.55) 4226.55,6929.57 ccw(c4226.55,6854.6) JP2.2@4173.53,6907.62 ; JP2.2@4129.62,7104.47 cw(c4076.6,7051.45) 4151.57,7051.45 cw(c4226.55,7051.45) 4173.53,7104.47 cw(c4226.55,7051.45) 4226.55,7126.43 cw(c4226.55,7201.4) JP2.2@4173.53,7148.38 ; JP2.2@4309.5,6890.65 ccw(c4215.51,6796.66) 4215.51,6929.57 ccw(c4215.51,7062.49) JP2.2@4309.5,6968.5 ; JP2.2@4309.5,7087.5 ccw(c4215.51,6993.51) 4215.51,7126.43 ccw(c4215.51,7259.34) JP2.2@4309.5,7165.35 ; JP2.2@4315.15,6896.3 ccw(c4234.82,6815.97) 4234.82,6929.57 ccw(c4234.82,7043.18) JP2.2@4315.15,6962.85 ; JP2.2@4315.15,7093.15 ccw(c4234.82,7012.82) 4234.82,7126.43 ccw(c4234.82,7240.03) JP2.2@4315.15,7159.7 ; JP2.2@4320.81,6901.96 ccw(c4254.14,6835.29) 4254.14,6929.57 ccw(c4254.14,7023.86) JP2.2@4320.81,6957.19 ; JP2.2@4320.81,7098.81 ccw(c4254.14,7032.14) 4254.14,7126.42 ccw(c4254.14,7220.71) JP2.2@4320.81,7154.04 ; JP2.2@4326.47,6907.62 ccw(c4273.45,6854.6) 4273.45,6929.57 ccw(c4273.45,7004.55) JP2.2@4326.47,6951.53 ; JP2.2@4326.47,7104.47 ccw(c4273.45,7051.45) 4273.45,7126.43 ccw(c4273.45,7201.4) JP2.2@4326.47,7148.38 ; JP2.2@4348.43,6929.57 JP2.2@4151.57,6929.57 JP2.2@4151.57,7126.43 4482.43,7126.43 4497,7141 4497,7393 4579,7475 4579,7512.46 4701,7634.46 4701,7688 4745.35,7732.35 U1.177@4937.69,7732.35 ; JP2.2@4370.38,7104.47 cw(c4423.4,7051.45) 4423.4,7126.43 cw(c4423.4,7201.4) JP2.2@4370.38,7148.38 ; JP2.2@4376.04,7098.81 cw(c4442.71,7032.14) 4442.71,7126.42 cw(c4442.71,7220.71) JP2.2@4376.04,7154.04 ; JP2.2@4381.7,7093.15 cw(c4462.03,7012.82) 4462.03,7126.43 cw(c4462.03,7240.03) JP2.2@4381.7,7159.7 ; JP2.2@4387.35,7087.5 cw(c4481.34,6993.51) 4481.34,7126.43 cw(c4481.34,7259.34) JP2.2@4387.35,7165.35 ; 4609.86,7543.33 cw(c4640,7513.19) R7.1@4640,7555.81 ; 4614.62,7548.08 ccw(c4591.2,7571.5) R7.1@4624.31,7571.5 ; R7.1@4623.52,7556.98 cw(c4640,7540.51) R7.1@4640,7563.81 ; R7.1@4640,7583.12 ccw(c4640,7606.42) R7.1@4656.48,7589.94 ; R7.1@4640,7591.12 ccw(c4640,7633.74) 4670.14,7603.6 ; R7.1@4655.69,7575.43 cw(c4688.8,7575.43) 4665.38,7598.85
LVDS2_INP: JP2.1 R7.2 U1.178 | length 1982.1
  TopLayer w8: JP2.1@4250,7028 4419,7028 4518,7127 4518,7384.54 4684,7550.54 4684,7585 4721,7622 4721,7675 4758.66,7712.66 U1.178@4937.69,7712.66 ; JP2.1@4271.96,7006.04 cw(c4324.97,6953.03) 4324.97,7028 cw(c4324.97,7102.97) JP2.1@4271.96,7049.96 ; JP2.1@4277.62,7000.38 cw(c4344.29,6933.71) 4344.29,7028 cw(c4344.29,7122.29) JP2.1@4277.62,7055.62 ; JP2.1@4283.27,6994.73 cw(c4363.6,6914.4) 4363.6,7028 cw(c4363.6,7141.6) JP2.1@4283.27,7061.27 ; JP2.1@4288.93,6989.07 cw(c4382.91,6895.09) 4382.91,7028 cw(c4382.91,7160.91) JP2.1@4288.93,7066.93 ; 4609.86,7476.4 cw(c4640,7446.26) R7.2@4640,7488.88 ; 4614.62,7481.15 ccw(c4591.2,7504.57) R7.2@4624.31,7504.57 ; R7.2@4623.52,7490.06 cw(c4640,7473.58) R7.2@4640,7496.88 ; R7.2@4640,7516.19 ccw(c4640,7539.49) R7.2@4656.48,7523.02 ; R7.2@4640,7524.19 ccw(c4640,7566.81) 4670.14,7536.67 ; R7.2@4655.69,7508.5 cw(c4688.8,7508.5) 4665.38,7531.92
LVDS3_INN: JP3.2 R8.1 U1.173 | length 5910.7
  TopLayer w8: JP3.2@4112.65,7428.5 ccw(c4018.66,7522.49) 4151.57,7522.49 ccw(c4284.49,7522.49) 4190.5,7428.5 ccw(c4284.49,7522.49) 4284.49,7389.57 ccw(c4284.49,7256.66) JP3.2@4190.5,7350.65 ; JP3.2@4112.65,7547.5 cw(c4018.66,7453.51) 4151.57,7453.51 cw(c4284.49,7453.51) 4190.5,7547.5 cw(c4284.49,7453.51) 4284.49,7586.43 cw(c4284.49,7719.34) JP3.2@4190.5,7625.35 ; JP3.2@4118.3,7422.85 ccw(c4037.97,7503.18) 4151.57,7503.18 ccw(c4265.18,7503.18) 4184.85,7422.85 ccw(c4265.18,7503.18) 4265.18,7389.57 ccw(c4265.18,7275.97) JP3.2@4184.85,7356.3 ; JP3.2@4118.3,7553.15 cw(c4037.97,7472.82) 4151.57,7472.82 cw(c4265.18,7472.82) 4184.85,7553.15 cw(c4265.18,7472.82) 4265.18,7586.43 cw(c4265.18,7700.03) JP3.2@4184.85,7619.7 ; JP3.2@4123.96,7417.19 ccw(c4057.29,7483.86) 4151.57,7483.86 ccw(c4245.86,7483.86) 4179.19,7417.19 ccw(c4245.86,7483.86) 4245.86,7389.58 ccw(c4245.86,7295.29) JP3.2@4179.19,7361.96 ; JP3.2@4123.96,7558.81 cw(c4057.29,7492.14) 4151.57,7492.14 cw(c4245.86,7492.14) 4179.19,7558.81 cw(c4245.86,7492.14) 4245.86,7586.42 cw(c4245.86,7680.71) JP3.2@4179.19,7614.04 ; JP3.2@4129.62,7411.53 ccw(c4076.6,7464.55) 4151.57,7464.55 ccw(c4226.55,7464.55) 4173.53,7411.53 ccw(c4226.55,7464.55) 4226.55,7389.57 ccw(c4226.55,7314.6) JP3.2@4173.53,7367.62 ; JP3.2@4129.62,7564.47 cw(c4076.6,7511.45) 4151.57,7511.45 cw(c4226.55,7511.45) 4173.53,7564.47 cw(c4226.55,7511.45) 4226.55,7586.43 cw(c4226.55,7661.4) JP3.2@4173.53,7608.38 ; JP3.2@4309.5,7350.65 ccw(c4215.51,7256.66) 4215.51,7389.57 ccw(c4215.51,7522.49) JP3.2@4309.5,7428.5 ; JP3.2@4309.5,7547.5 ccw(c4215.51,7453.51) 4215.51,7586.43 ccw(c4215.51,7719.34) JP3.2@4309.5,7625.35 ; JP3.2@4315.15,7356.3 ccw(c4234.82,7275.97) 4234.82,7389.57 ccw(c4234.82,7503.18) JP3.2@4315.15,7422.85 ; JP3.2@4315.15,7553.15 ccw(c4234.82,7472.82) 4234.82,7586.43 ccw(c4234.82,7700.03) JP3.2@4315.15,7619.7 ; JP3.2@4320.81,7361.96 ccw(c4254.14,7295.29) 4254.14,7389.57 ccw(c4254.14,7483.86) JP3.2@4320.81,7417.19 ; JP3.2@4320.81,7558.81 ccw(c4254.14,7492.14) 4254.14,7586.42 ccw(c4254.14,7680.71) JP3.2@4320.81,7614.04 ; JP3.2@4326.47,7367.62 ccw(c4273.45,7314.6) 4273.45,7389.57 ccw(c4273.45,7464.55) JP3.2@4326.47,7411.53 ; JP3.2@4326.47,7564.47 ccw(c4273.45,7511.45) 4273.45,7586.43 ccw(c4273.45,7661.4) JP3.2@4326.47,7608.38 ; JP3.2@4348.43,7389.57 JP3.2@4151.57,7389.57 JP3.2@4151.57,7586.43 4472.96,7586.43 ; JP3.2@4371.39,7565.52 cw(c4418.67,7522.51) 4418.67,7586.43 cw(c4418.67,7650.34) JP3.2@4371.39,7607.33 ; JP3.2@4377.31,7560.14 cw(c4436.76,7506.05) 4436.76,7586.43 cw(c4436.76,7666.8) JP3.2@4377.31,7612.71 ; JP3.2@4383.23,7554.76 cw(c4454.86,7489.58) 4454.86,7586.43 cw(c4454.86,7683.27) JP3.2@4383.23,7618.09 ; JP3.2@4389.15,7549.37 cw(c4472.95,7473.12) 4472.95,7586.42 ; JP3.2@4389.15,7623.48 ccw(c4472.95,7699.73) 4472.95,7586.43 ; 4609.86,7723.33 cw(c4640,7693.19) R8.1@4640,7735.81 ; 4614.62,7728.08 ccw(c4591.2,7751.5) R8.1@4624.31,7751.5 ; R8.1@4623.52,7736.98 cw(c4640,7720.51) R8.1@4640,7743.81 ; R8.1@4651.83,7743.16 cw(c4674.46,7723.45) 4674.46,7753.46 ; R8.1@4651.83,7763.77 ccw(c4674.46,7783.48) 4674.46,7753.46 ; U1.173@4937.69,7811.09 4732.09,7811.09 4674.46,7753.46 ; 4472.96,7586.43 R8.1@4640,7753.46 4674.46,7753.46
LVDS3_INP: JP3.1 R8.2 U1.174 | length 1927.4
  TopLayer w8: JP3.1@4250,7488 4401.46,7488 4620,7706.54 ; JP3.1@4271.96,7466.04 cw(c4324.97,7413.03) 4324.97,7488 cw(c4324.97,7562.97) JP3.1@4271.96,7509.96 ; JP3.1@4277.62,7460.38 cw(c4344.29,7393.71) 4344.29,7488 cw(c4344.29,7582.29) JP3.1@4277.62,7515.62 ; JP3.1@4283.27,7454.73 cw(c4363.6,7374.4) 4363.6,7488 cw(c4363.6,7601.6) JP3.1@4283.27,7521.27 ; JP3.1@4288.93,7449.07 cw(c4382.91,7355.09) 4382.91,7488 cw(c4382.91,7620.91) JP3.1@4288.93,7526.93 ; 4541.58,7628.11 cw(c4640,7529.69) R8.2@4640,7668.88 ; 4555.24,7641.77 cw(c4640,7557.01) R8.2@4640,7676.88 ; 4568.89,7655.43 cw(c4640,7584.32) R8.2@4640,7684.88 ; 4582.55,7669.09 cw(c4640,7611.64) R8.2@4640,7692.88 ; 4596.21,7682.74 cw(c4640,7638.95) R8.2@4640,7700.88 ; R8.2@4640,7686.54 4744.87,7791.4 U1.174@4937.69,7791.4 ; R8.2@4640,7696.19 ccw(c4640,7719.49) R8.2@4656.48,7703.01 ; R8.2@4640,7704.19 ccw(c4640,7746.81) 4670.14,7716.67 ; R8.2@4655.69,7688.5 cw(c4688.8,7688.5) 4665.38,7711.92
LVDS3_OUTN: JP5.3 R3.1 R12.1 | length 719.1
  TopLayer w8: JP5.3@4360,8700 4543.54,8700 R3.1@4590,8746.46 4670,8746.46 R12.1@4696.54,8773 ; JP5.3@4372.39,8687.61 cw(c4402.32,8657.68) 4402.32,8700 cw(c4402.32,8742.32) JP5.3@4372.39,8712.39 ; JP5.3@4378.05,8681.95 cw(c4421.63,8638.37) 4421.63,8700 cw(c4421.63,8761.63) JP5.3@4378.05,8718.05 ; 4559.86,8716.33 cw(c4590,8686.19) R3.1@4590,8728.81 ; 4564.62,8721.08 ccw(c4541.2,8744.5) R3.1@4574.31,8744.5 ; R3.1@4573.52,8729.98 cw(c4590,8713.51) R3.1@4590,8736.81 ; R3.1@4601.09,8735.37 cw(c4627.87,8708.6) 4627.87,8746.46 cw(c4627.87,8784.33) R3.1@4601.09,8757.56 ; 4670.99,8747.45 ccw(c4651.05,8767.39) R12.1@4679.01,8770.99 ; 4671.15,8747.62 cw(c4694.57,8724.2) R12.1@4694.57,8757.32
LVDS3_OUTP: JP5.1 R3.2 R11.1 | length 740.7
  TopLayer w8: JP5.1@4360,8600 4439.54,8679.54 R3.2@4590,8679.54 4596.54,8673 R11.1@4696.54,8673 ; JP5.1@4360,8617.53 ccw(c4360,8659.84) 4389.92,8629.92 ccw(c4419.84,8600) JP5.1@4377.53,8600 ; JP5.1@4360,8625.53 ccw(c4360,8687.16) 4403.58,8643.58 ccw(c4447.16,8600) JP5.1@4385.53,8600 ; R3.2@4578.91,8668.44 ccw(c4552.13,8641.67) 4552.13,8679.54 ccw(c4552.13,8717.4) R3.2@4578.91,8690.63 ; R3.2@4595.43,8683 ccw(c4619.58,8707.15) 4619.58,8673 ; R3.2@4601.09,8666.48 cw(c4616.84,8650.73) 4616.84,8673 ; R3.2@4601.09,8688.66 ccw(c4638.89,8726.46) 4638.89,8673 ; R11.1@4683.48,8661.91 ccw(c4656.7,8635.13) 4656.7,8673 ccw(c4656.7,8710.87) R11.1@4683.48,8684.09
LVDS6_INN: JP5.4 R5.1 U1.164 | length 1499.6
  TopLayer w8: v1@4777,8153 cw(c4777,8143.34) 4783.83,8150.17 cw(c4790.66,8157) v1@4781,8157 ; v1(4777,8157) 4813.46,8120.54 ; v1@4782.46,8151.54 cw(c4730.93,8100) R5.1@4803.81,8100 ; 4796.12,8137.88 cw(c4758.24,8100) R5.1@4811.81,8100 ; R5.1@4809.34,8115.13 ccw(c4807.86,8120.53) 4813.46,8120.53 ; 4809.78,8124.22 cw(c4785.56,8100) R5.1@4819.81,8100 ; R5.1@4815.43,8084.31 cw(c4815.43,8042.66) 4844.88,8072.12 ; R5.1@4815.43,8092.31 cw(c4815.43,8069.98) R5.1@4831.23,8085.77 ; R5.1@4817.59,8115.13 cw(c4819.06,8120.53) 4813.46,8120.53 ; R5.1@4831.12,8100 ccw(c4865.2,8100) 4841.1,8075.9 ; U1.164@4937.69,7988.25 4902.75,7988.25 4876,8015 4876,8041 4817,8100 R5.1@4813.46,8100 4813.46,8120.54
  BottomLayer w8: JP5.4@4260,8700 4301,8659 ; JP5.4@4260.77,8682.49 cw(c4262.38,8646.08) 4288.15,8671.85 cw(c4313.92,8697.62) JP5.4@4277.51,8699.23 ; JP5.4@4261.13,8674.5 cw(c4263.46,8621.47) 4301,8659 ; JP5.4@4285.5,8698.87 ccw(c4338.53,8696.54) 4301,8659 ; v1@4774.17,8154.17 ccw(c4767.34,8147.34) 4767.34,8157 ccw(c4767.34,8166.66) v1@4774.17,8159.83 ; v1(4777,8157) 4762,8157 4492,8427 4492,8603 4436,8659 4301,8659
LVDS6_INP: JP5.2 R5.2 U1.165 | length 1465.1
  TopLayer w8: R5.2@4735.44,8111.09 ccw(c4708.67,8137.87) 4746.54,8137.87 ccw(c4784.4,8137.87) R5.2@4757.63,8111.09 ; v1@4743.71,8143.64 cw(c4736.88,8136.81) 4746.54,8136.81 cw(c4756.19,8136.81) v1@4749.36,8143.64 ; v1(4746.54,8146.46) 4746.54,8082.46 4776,8053 4839,8053 4859,8033 4859,8008 4898.43,7968.57 U1.165@4937.69,7968.57 ; R5.2@4748.23,8100.15 ccw(c4764.6,8090.96) 4751.32,8077.68 ; R5.2@4755.2,8096.24 ccw(c4774.16,8085.59) 4758.78,8070.22 ; R5.2@4762.18,8092.32 ccw(c4783.71,8080.22) 4766.25,8062.75
  BottomLayer w8: JP5.2@4260,8600 4303,8643 ; JP5.2@4260.17,8617.53 ccw(c4260.56,8658.49) 4289.52,8629.52 ccw(c4318.49,8600.56) JP5.2@4277.53,8600.17 ; JP5.2@4260.24,8625.53 ccw(c4260.81,8685.18) 4303,8643 ; JP5.2@4285.53,8600.24 cw(c4345.18,8600.81) 4303,8643 ; v1@4742.54,8146.46 ccw(c4732.88,8146.46) 4739.71,8153.29 ccw(c4746.54,8160.12) v1@4746.54,8150.46 ; v1(4746.54,8146.46) 4473.75,8419.25 4473.75,8596.25 4427,8643 4303,8643
LVDS_CLKN: JP4.2 R2.1 U1.152 | length 5906
  TopLayer w8: JP4.2@4102.65,8280.5 ccw(c4008.66,8374.49) 4141.57,8374.49 ccw(c4274.49,8374.49) 4180.5,8280.5 ccw(c4274.49,8374.49) 4274.49,8241.57 ; JP4.2@4102.65,8399.5 cw(c4008.66,8305.51) 4141.57,8305.51 cw(c4274.49,8305.51) 4180.5,8399.5 cw(c4274.49,8305.51) 4274.49,8438.43 ; JP4.2@4108.3,8274.85 ccw(c4027.97,8355.18) 4141.57,8355.18 ccw(c4255.18,8355.18) 4174.85,8274.85 ccw(c4255.18,8355.18) 4255.18,8241.58 ; JP4.2@4108.3,8405.15 cw(c4027.97,8324.82) 4141.57,8324.82 cw(c4255.18,8324.82) 4174.85,8405.15 cw(c4255.18,8324.82) 4255.18,8438.42 cw(c4255.18,8552.03) JP4.2@4174.85,8471.7 ; JP4.2@4113.96,8269.19 ccw(c4047.29,8335.86) 4141.57,8335.86 ccw(c4235.86,8335.86) 4169.19,8269.19 ccw(c4235.86,8335.86) 4235.86,8241.58 ccw(c4235.86,8147.29) JP4.2@4169.19,8213.96 ; JP4.2@4113.96,8410.81 cw(c4047.29,8344.14) 4141.57,8344.14 cw(c4235.86,8344.14) 4169.19,8410.81 cw(c4235.86,8344.14) 4235.86,8438.42 ; JP4.2@4119.62,8263.53 ccw(c4066.6,8316.55) 4141.57,8316.55 ccw(c4216.55,8316.55) 4163.53,8263.53 ccw(c4216.55,8316.55) 4216.55,8241.57 ; JP4.2@4119.62,8416.47 cw(c4066.6,8363.45) 4141.57,8363.45 cw(c4216.55,8363.45) 4163.53,8416.47 cw(c4216.55,8363.45) 4216.55,8438.43 ; JP4.2@4163.53,8219.62 cw(c4216.55,8166.6) 4216.55,8241.58 ; JP4.2@4163.53,8460.38 ccw(c4216.55,8513.4) 4216.55,8438.42 ; JP4.2@4169.19,8466.04 ccw(c4235.86,8532.71) 4235.86,8438.43 ; JP4.2@4174.85,8208.3 cw(c4255.18,8127.97) 4255.18,8241.57 ; JP4.2@4180.5,8202.65 cw(c4274.49,8108.66) 4274.49,8241.58 ; JP4.2@4180.5,8477.35 ccw(c4274.49,8571.34) 4274.49,8438.42 ; 4205.51,8241.57 ccw(c4205.51,8374.49) JP4.2@4299.5,8280.5 ; 4205.51,8241.58 cw(c4205.51,8108.66) JP4.2@4299.5,8202.65 ; 4205.51,8438.42 ccw(c4205.51,8571.34) JP4.2@4299.5,8477.35 ; 4205.51,8438.43 cw(c4205.51,8305.51) JP4.2@4299.5,8399.5 ; 4224.82,8241.57 cw(c4224.82,8127.97) JP4.2@4305.15,8208.3 ; 4224.82,8241.58 ccw(c4224.82,8355.18) JP4.2@4305.15,8274.85 ; 4244.14,8438.42 cw(c4244.14,8344.14) JP4.2@4310.81,8410.81 ; 4244.14,8438.43 ccw(c4244.14,8532.71) JP4.2@4310.81,8466.04 ; 4263.45,8241.57 ccw(c4263.45,8316.55) JP4.2@4316.47,8263.53 ; 4263.45,8241.58 cw(c4263.45,8166.6) JP4.2@4316.47,8219.62 ; 4263.45,8438.42 ccw(c4263.45,8513.4) JP4.2@4316.47,8460.38 ; 4263.45,8438.43 cw(c4263.45,8363.45) JP4.2@4316.47,8416.47 ; JP4.2@4305.15,8405.15 ccw(c4224.82,8324.82) 4224.82,8438.42 ccw(c4224.82,8552.03) JP4.2@4305.15,8471.7 ; JP4.2@4310.81,8213.96 ccw(c4244.14,8147.29) 4244.14,8241.58 ccw(c4244.14,8335.86) JP4.2@4310.81,8269.19 ; JP4.2@4338.43,8241.58 JP4.2@4141.57,8241.58 JP4.2@4141.57,8438.42 4455.04,8438.42 ; JP4.2@4362.4,8418.69 cw(c4404.2,8384.29) 4404.2,8438.43 ; JP4.2@4362.4,8458.16 ccw(c4404.2,8492.56) 4404.2,8438.42 ; JP4.2@4368.58,8413.61 cw(c4421.15,8370.35) 4421.15,8438.42 cw(c4421.15,8506.5) JP4.2@4368.58,8463.24 ; JP4.2@4374.76,8408.52 cw(c4438.09,8356.4) 4438.09,8438.43 ; JP4.2@4374.76,8468.33 ccw(c4438.09,8520.45) 4438.09,8438.42 ; JP4.2@4380.94,8403.44 cw(c4455.03,8342.46) 4455.03,8438.42 ; JP4.2@4380.94,8473.41 ccw(c4455.03,8534.39) 4455.03,8438.43 ; 4469.86,8423.6 ccw(c4500,8453.74) R2.1@4500,8411.12 ; 4474.62,8418.85 cw(c4451.2,8395.43) R2.1@4484.31,8395.43 ; R2.1@4483.52,8409.94 ccw(c4500,8426.42) R2.1@4500,8403.12 ; R2.1@4500,8375.81 cw(c4500,8333.19) 4530.14,8363.33 ; R2.1@4500,8383.81 cw(c4500,8360.51) R2.1@4516.48,8376.98 ; R2.1@4515.69,8391.5 ccw(c4548.8,8391.5) 4525.38,8368.08 ; U1.152@4937.69,8224.47 4628.53,8224.47 4559,8294 4559,8334.46 4455.04,8438.42
LVDS_CLKP: JP4.1 R2.2 U1.153 | length 1620.8
  TopLayer w8: JP4.1@4240,8340 4486.54,8340 4621.75,8204.79 U1.153@4937.69,8204.79 ; JP4.1@4261.96,8318.04 cw(c4314.97,8265.03) 4314.97,8340 cw(c4314.97,8414.97) JP4.1@4261.96,8361.96 ; JP4.1@4267.62,8312.38 cw(c4334.29,8245.71) 4334.29,8340 cw(c4334.29,8434.29) JP4.1@4267.62,8367.62 ; JP4.1@4273.27,8306.73 cw(c4353.6,8226.4) 4353.6,8340 cw(c4353.6,8453.6) JP4.1@4273.27,8373.27 ; JP4.1@4278.93,8301.07 cw(c4372.91,8207.09) 4372.91,8340 cw(c4372.91,8472.91) JP4.1@4278.93,8378.93 ; 4434.38,8340 cw(c4434.38,8262.88) R2.2@4488.91,8317.41 ; 4453.69,8340 cw(c4453.69,8282.2) R2.2@4494.57,8323.07 ; 4473.01,8340 cw(c4473.01,8301.51) R2.2@4500.22,8328.73 ; R2.2@4500,8308.88 cw(c4500,8266.26) 4530.14,8296.4 ; R2.2@4500,8316.88 cw(c4500,8293.58) R2.2@4516.48,8310.06 ; R2.2@4515.69,8324.57 ccw(c4548.8,8324.57) 4525.38,8301.15
LVDS_PLLN: JP9.1 R6.1 R10.1 | length 594.8
  TopLayer w8: R6.1@4593.4,8469.66 ccw(c4588.6,8480) 4600,8480 ; R6.1@4600,8435.81 cw(c4600,8393.19) 4630.14,8423.33 ; R6.1@4600,8443.81 cw(c4600,8420.51) R6.1@4616.48,8436.98 ; R6.1@4606.6,8469.66 cw(c4611.4,8480) 4600,8480 ; R6.1@4615.69,8451.5 ccw(c4648.8,8451.5) 4625.38,8428.08 ; JP9.1@4654.47,8560 cw(c4592.84,8560) 4636.42,8516.42 cw(c4680,8472.84) JP9.1@4680,8534.47 ; JP9.1@4662.47,8560 cw(c4620.16,8560) 4650.08,8530.08 cw(c4680,8500.16) JP9.1@4680,8542.47 ; JP9.1@4680,8560 4600,8480 ; R10.1@4693.48,8388.91 ccw(c4666.7,8362.13) 4666.7,8400 ccw(c4666.7,8437.87) R10.1@4693.48,8411.09 ; R10.1@4706.54,8400 4653.46,8400 R6.1@4600,8453.46 4600,8480
LVDS_PLLP: JP9.2 R6.2 R9.1 | length 742.2
  TopLayer w8: JP9.2@4556.78,8549.4 cw(c4544.3,8543.7) 4554,8534 ; JP9.2@4569.4,8536.78 ccw(c4563.7,8524.3) 4554,8534 ; 4569.86,8416.67 ccw(c4600,8446.81) R6.2@4600,8404.19 ; 4574.62,8411.92 cw(c4551.2,8388.5) R6.2@4584.31,8388.5 ; JP9.2@4580,8560 4554,8534 ; R6.2@4583.52,8403.01 ccw(c4600,8419.49) R6.2@4600,8396.19 ; R6.2@4600,8368.88 cw(c4600,8277.98) 4664.28,8342.26 ; R6.2@4600,8376.88 cw(c4600,8305.29) 4650.62,8355.91 ; R6.2@4600,8384.88 cw(c4600,8332.61) 4636.96,8369.57 ; R6.2@4600,8392.88 cw(c4600,8359.92) 4623.31,8383.23 ; R6.2@4615.23,8382.8 cw(c4620,8381.63) 4620,8386.54 ; R6.2@4615.23,8390.27 ccw(c4620,8391.44) 4620,8386.54 ; 4676.4,8330.14 cw(c4646.26,8300) R9.1@4688.88,8300 ; 4681.15,8325.38 ccw(c4704.57,8348.8) R9.1@4704.57,8315.68 ; R9.1@4690.06,8316.48 cw(c4673.58,8300) R9.1@4696.88,8300 ; R9.1@4706.54,8300 4620,8386.54 ; 4554,8534 4554,8432.54 R6.2@4600,8386.54 4620,8386.54
NCE: JP11.6 R25.2 U1.33 | length 1643.9
  TopLayer w6: U1.33@6274.31,8303.21 v1(6328.79,8303.21) ; U1.33@6299.98,8301.16 cw(c6304.94,8296.2) 6304.94,8303.21 cw(c6304.94,8310.23) U1.33@6299.98,8305.27 ; v1@6325.25,8299.68 ccw(c6316.72,8291.14) 6316.72,8303.21 ccw(c6316.72,8315.28) v1@6325.25,8306.75 ; v1@6509,8118 cw(c6509,8105.93) 6517.54,8114.46 cw(c6526.07,8123) v1@6514,8123 ; v1(6509,8123) 6668,7964 6668,7877 6694,7851 6769,7851 6886.54,7733.46 R25.2@6886.54,7680 ; JP11.6@6792,7800 ccw(c6724.4,7800) 6772.2,7847.8 ccw(c6820,7895.6) JP11.6@6820,7828 ; JP11.6@6798,7800 ccw(c6744.89,7800) 6782.44,7837.56 ccw(c6820,7875.11) JP11.6@6820,7822 ; JP11.6@6804,7800 ccw(c6765.37,7800) 6792.69,7827.31 ccw(c6820,7854.63) JP11.6@6820,7816 ; JP11.6@6820,7772 cw(c6820,7704.4) 6867.8,7752.2 cw(c6915.6,7800) JP11.6@6848,7800 ; JP11.6@6820,7778 cw(c6820,7724.89) 6857.56,7762.44 cw(c6895.11,7800) JP11.6@6842,7800 ; JP11.6@6820,7784 cw(c6820,7745.37) 6847.31,7772.69 cw(c6874.63,7800) JP11.6@6836,7800 ; R25.2@6874.74,7691.8 ccw(c6846.25,7720.28) 6886.54,7720.28 ccw(c6926.82,7720.28) R25.2@6898.33,7691.8 ; R25.2@6878.98,7687.56 ccw(c6860.74,7705.8) 6886.54,7705.8 ccw(c6912.33,7705.8) R25.2@6894.09,7687.56
  BottomLayer w6: v1@6328.79,8298.21 cw(c6328.79,8286.14) 6337.32,8294.68 cw(c6345.86,8303.21) v1@6333.79,8303.21 ; v1(6328.79,8303.21) v1(6509,8123) ; v1@6504,8123 ccw(c6491.93,8123) 6500.46,8131.54 ccw(c6509,8140.07) v1@6509,8128
NCEO: U1.32
NetC54_2: C27.2 U13.18 | length 363.7
  TopLayer w12: C27.2@8320,9610.88 cw(c8320,9573.09) 8346.72,9599.81 ; C27.2@8320,9626.54 8387.54,9559 8466,9559 8511.18,9513.82 U13.18@8511.18,9439.84 ; C27.2@8333.69,9624.57 ccw(c8361.97,9624.57) 8341.97,9604.57
NetC64_2: C28.2 U13.17 | length 278.7
  TopLayer w12: C28.2@8440,9610.88 cw(c8440,9588.87) 8455.57,9604.43 ; C28.2@8440,9626.54 8440,9620 8536.77,9523.23 U13.17@8536.77,9439.84 ; C28.2@8453.68,9624.57 ccw(c8497.75,9624.57) 8466.59,9593.41
NetC102_1: C118.1 U13.5 | length 224
  TopLayer w12: v3@8558.12,9118.61 ccw(c8547.88,9128.85) 8562.36,9128.85 ccw(c8576.85,9128.85) v3@8566.61,9118.61 ; v3(8562.36,9114.36) U13.5@8562.36,9180
  BottomLayer w12: C118.1@8536.86,9069.68 ccw(c8513.5,9093.04) 8546.54,9093.04 ccw(c8579.57,9093.04) C118.1@8556.21,9069.68 ; C118.1@8546.54,9060 8546.54,9098.54 v3(8562.36,9114.36) ; v3@8556.36,9114.36 cw(c8541.88,9114.36) 8552.12,9104.12 cw(c8562.36,9093.88) v3@8562.36,9108.36
NetC102_2: C118.2 L1.1 U13.6 U13.7 U13.8 U13.9 U13.10 | length 122.2
  BottomLayer w12: C118.2@8603.79,9050.32 cw(c8581.55,9028.08) 8613,9028.08 ; v3@8608.76,9016.24 ccw(c8598.51,9026.49) 8613,9026.49 ccw(c8627.49,9026.49) v3@8617.24,9016.24 ; v3(8613,9012) C118.2@8613,9059.54 ; 8613,9025.84 cw(c8647.62,9025.84) C118.2@8623.14,9050.32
